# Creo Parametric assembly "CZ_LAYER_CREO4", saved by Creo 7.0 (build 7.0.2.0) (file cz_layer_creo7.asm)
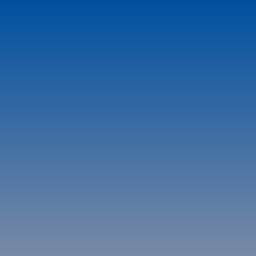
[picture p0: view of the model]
Units: Custom; MM, KILOGRAM, SECS

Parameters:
  BEARBEITER = "."
  ERSTELLUNGSDATUM = "."
  KONSTRUKTIONSGRUPPE = "."
  ZEICHNUNGSNUMMER = "000000-0000-000/01"
  TEILDOKUMENT = "001"
  VERSION = "01"
  MATERIALNUMMER = "000000-0000-000"
  KOMP_STUFE = "G"
  KOMP_CHAR = "M"
  BENENNUNG = "XXXXX"

Other parameters: PREIS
